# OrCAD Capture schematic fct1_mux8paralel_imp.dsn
size A
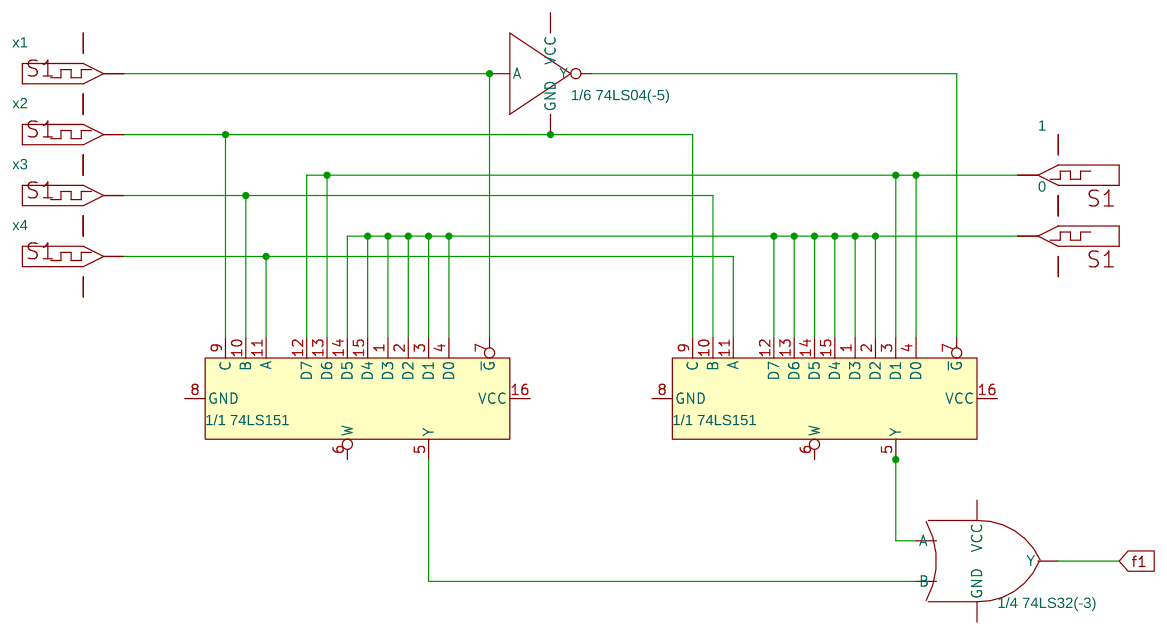
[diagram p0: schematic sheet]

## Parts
0  DigStim1
1  DigStim1
U1  1/4 74LS32(-3)  [DIP.100/14/W.300/L.800]  (section A)
U2  1/1 74LS151  [DIP.100/16/W.300/L.900]
U3  1/1 74LS151  [DIP.100/16/W.300/L.900]
U4  1/6 74LS04(-5)  [DIP.100/14/W.300/L.800]  (section A)
x1  DigStim1
x2  DigStim1
x3  DigStim1
x4  DigStim1

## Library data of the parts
0 1 x1-x4 = DigStim1
U1 = 74LS32
U2 U3 = 74LS151
U4 = 74LS04

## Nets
GND: 0.3(GND) 1.3(GND) U1.7(GND) U2.8(GND) U3.8(GND) U4.7(GND) x1.3(GND) x2.3(GND) x3.3(GND) x4.3(GND)
VCC: 0.2(VCC) 1.2(VCC) U1.14(VCC) U2.16(VCC) U3.16(VCC) U4.14(VCC) x1.2(VCC) x2.2(VCC) x3.2(VCC) x4.2(VCC)
f1: U1.3(Y)
N14749: U1.2(B) U3.5(Y)
N14756: U1.1(A) U2.5(Y)
N15090: U2.11(A) U3.11(A) x4.OUT
N15106: U2.10(B) U3.10(B) x3.OUT
N15140: U2.9(C) U3.9(C) x2.OUT
N15169: U3.7(~{G}) U4.1(A) x1.OUT
N15197: U2.7(~{G}) U4.2(Y)
N17259: 0.OUT U2.1(D3) U2.2(D2) U2.12(D7) U2.13(D6) U2.14(D5) U2.15(D4) U3.1(D3) U3.2(D2) U3.3(D1) U3.4(D0) U3.14(D5) U3.15(D4)
N17357: 1.OUT U2.3(D1) U2.4(D0) U3.12(D7) U3.13(D6)

Not connected (* = marked no-connect by the designer): U2 6(W); U3 6(W)
